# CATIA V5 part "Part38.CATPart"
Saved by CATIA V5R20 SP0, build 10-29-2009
Part number: FA 168700-2 comprimido
Revision: ANY
Definition: UNKNOWN
Nomenclature: FA 168700-2 comprimido
Source: Unknown
Bounding box of the stored display mesh (mm): x -2.8 to 2.8, y 0 to 4.04, z -2.8 to 2.8
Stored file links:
  C:\Users\Utente\Desktop\IO LAVORO\3D X SITO CF\CUMSA\3D files FA\FA 2007SF\Part38.CATPart

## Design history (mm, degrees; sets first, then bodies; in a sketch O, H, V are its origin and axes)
Body1 "Cortar-Extruir1" (main body)
  Solid1: solid without history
